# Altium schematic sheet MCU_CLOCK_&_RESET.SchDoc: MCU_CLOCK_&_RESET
size A4; Date: Not used; ApprovedBy: Not used; CheckedBy: Not used; Author: Not used; CompanyName: STMicroelectronics; DrawnBy: Not used; Engineer: Not used; Organization: Not used; Address1: Not used; Address2: Not used; Address3: Not used; Address4: Not used; DocumentNumber: 4; Revision: Not used; SheetNumber: 4; SheetTotal: 16
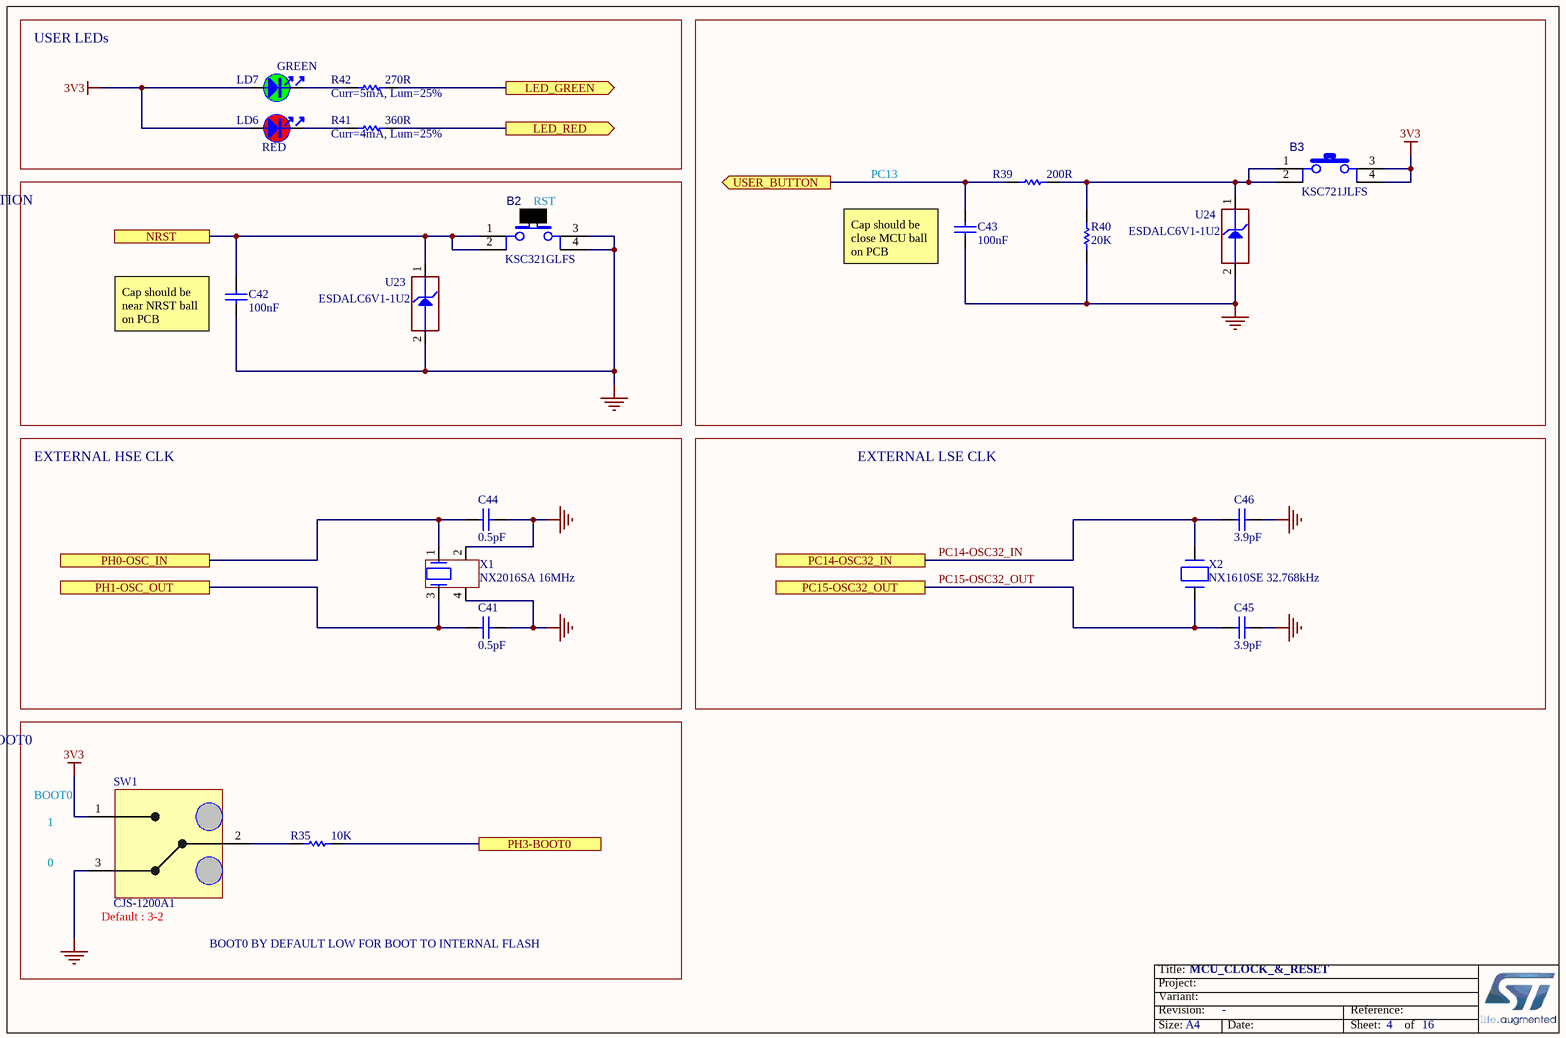
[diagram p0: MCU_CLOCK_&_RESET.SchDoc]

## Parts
B2  value KSC321GLFS  [SWI_C&K_KSC321GLFS_BLACK]  (hidden comment: SW_BLACK_KSC321GLFS)
B3  value KSC721JLFS  [SWI_C&K_KSC721JLFS_BLUE]  (hidden comment: SW_BLUE_KSC721JLFS)
C41  value 0.5pF  [C0402]  (hidden comment: Capacitor)
C42  value 100nF  [C0402]  (hidden comment: Capacitor)
C43  value 100nF  [C0402]
C44  value 0.5pF  [C0402]  (hidden comment: Capacitor)
C45  value 3.9pF  [C0402]  (hidden comment: Capacitor)
C46  value 3.9pF  [C0402]  (hidden comment: Capacitor)
LD6  value RED  [LED_0603_VISHAY_VLMS1300-GS08_RED_1A2K_H0P8]  (hidden comment: LED_red)
LD7  value GREEN  [LED_0603_OSRAM_LG-Q396-PS-35_GREEN_1A2K_H0P4]
R35  value 10K  [R0603]
R39  value 200R  [R0603]
R40  value 20K  [R0603]
R41  value 360R  [R0402]
R42  value 270R  [R0402]
SW1  CJS-1200A1  [SWI_CJS-1200A1]
U23  value ESDALC6V1-1U2  [ESD_ST0201]
U24  value ESDALC6V1-1U2  [ESD_ST0201]
X1  value NX2016SA 16MHz  [CRY_NX2016SA_4P]  (hidden comment: XTAL_4_PINS)
X2  value NX1610SE 32.768kHz  [CRY_NX1610SE_2P]  (hidden comment: XTAL_2_PINS)

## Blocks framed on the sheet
USER LEDs: LD6 LD7 R41 R42
PC13: B3 C43 R39 R40 U24
RESET FUNCTION: B2 C42 U23
EXTERNAL HSE CLK: C41 C44 X1
EXTERNAL LSE CLK: C45 C46 X2
PH3_BOOT0: R35 SW1

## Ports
LED_GREEN (out), LED_RED (out), NRST, PC14-OSC32_IN, PC15-OSC32_OUT, PH0-OSC_IN, PH1-OSC_OUT, PH3-BOOT0, USER_BUTTON (out)

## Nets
3V3: B3.3 B3.4 LD6.1 LD7.1 SW1.1
GND: B2.3 B2.4 C41.2 C42.1 C43.1 C44.2 C45.2 C46.2 R40.1 SW1.3 U23.2(GND) U24.2(GND) X1.2 X1.4
LED_GREEN: R42.2 ; port LED_GREEN
LED_RED: R41.2 ; port LED_RED
NRST: B2.1 B2.2 C42.2 U23.1(IO1) ; port NRST
PC14-OSC32_IN: C46.1 X2.2(X2) ; port PC14-OSC32_IN
PC15-OSC32_OUT: C45.1 X2.1(X1) ; port PC15-OSC32_OUT
PH0-OSC_IN: C44.1 X1.1 ; port PH0-OSC_IN
PH1-OSC_OUT: C41.1 X1.3 ; port PH1-OSC_OUT
PH3-BOOT0: R35.2 ; port PH3-BOOT0
USER_BUTTON: C43.2 R39.1 ; port USER_BUTTON
NetB3_1: B3.1 B3.2 R39.2 R40.2 U24.1(IO1)
NetLD6_2: LD6.2 R41.1
NetLD7_2: LD7.2 R42.1
NetR35_1: R35.1 SW1.2

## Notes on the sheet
- (near R42) Curr=5mA, Lum=25%
- (near R41) Curr=4mA, Lum=25%
- (near B2) RST
- (near C43) Cap should be close MCU ball on PCB
- (near C42) Cap should be near NRST ball on PCB
- (near SW1) BOOT0
- 1
- 0
- (near SW1) Default : 3-2
- BOOT0 BY DEFAULT LOW FOR BOOT TO INTERNAL FLASH

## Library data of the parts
B2 = MCD-00175: Switch HW BLACK High3.5mm 2Newtons; Part_Type: Misc; Manufacturer: C&K; Provided_By: SUBCO; Initial_Board_Reference: MB1274
B3 = MCD-01800: Switch HW BLUE High4.3mm 2.25 Newtons, BEND type; Part_Type: Misc; Manufacturer: C&K; Provided_By: SUBCO
C41 C44 = MCD-02215: Capacitor, MLCC, 0.5pF, 50V, C0G, +-0.1pF, 0402, T=0.5mm; Part_Preference: Recommended; Manufacturer: MURATA; Manufacturer_Part_Number: GJM1555C1HR50BB01D; Order_Code_RS: 723-5111P
C42 = MCD-00006: Capacitor, MLCC, 100nF, 16V, X7R, 10%, 0402, T=0.5mm; Manufacturer_Part_Number: CC0402KRX7R7BB104; Manufacturer: YAGEO; Provided_By: SUBCO; Initial_Board_Reference: MB1274
C43 = MCD-00006: Capacitor, MLCC, 100nF, 16V, X7R, 10%, 0402, T=0.5mm; Manufacturer_Part_Number: CC0402KRX7R7BB104; Manufacturer: YAGEO; Alternate_Manufacturer_Part_Number: GCM155R71C104KA55D; Alternate_Manufacturer: MURATA; Provided_By: SUBCO; ECCN_US: EAR99; ECCN_EU: NEC
C45 C46 = MCD-00556: Capacitor, MLCC, 3.9pF, 50V, NPO, +/-0.25pF, 0402, T=0.5mm; Part_Preference: Recommended; Manufacturer: YAGEO; Manufacturer_Part_Number: CC0402CRNPO9BN3R9; Component_Country_Of_Origin: China
LD6 = MCD-00587: LED Red, 0603 SMD, 2V Forward Voltage; Part_Type: Display; Manufacturer_Part_Number: VLMS1300-GS08; Manufacturer: VISHAY; Alternate_Manufacturer_Part_Number: LS Q976-NR-1; Alternate_Manufacturer: OSRAM OPTO SEMICONDUCTORS; Provided_By: SUBCO; Initial_Board_Reference: MB1331; Item Type: Item; Path: ws/MCD_ApplicationBoards/Lists/MCDPARTSdatabase
LD7 = MCD-00588: LED Green, 0603 SMD, Forward Voltage Typ=2V, Max=2.5V; Part_Type: Display; Manufacturer_Part_Number: LG Q396-PS-35; Manufacturer: OSRAM OPTO SEMICONDUCTORS; Alternate_Manufacturer_Part_Number: VLMTG1300-GS08; Alternate_Manufacturer: VISHAY SEMICONDUCTOR OPTO DIVISION; Provided_By: Subcon; Initial_Board_Reference: MB1331
R35 = MCD-00220: Resistor,10K,0603,1%,1/10W; Manufacturer_Part_Number: RC0603FR-0710KL; Manufacturer: YAGEO; Provided_By: Subcon; Initial_Board_Reference: MB1319
R39 = MCD-00418: Resistor,200R,0603,1%,1/10W; Manufacturer_Part_Number: RC0603FR-07200RL; Manufacturer: YAGEO; Provided_By: SUBCO; ECCN_US: EAR99; ECCN_EU: NEC
R40 = MCD-00422: Resistor,20K,0603,1%,1/10W; Manufacturer_Part_Number: RC0603FR-0720KL; Manufacturer: YAGEO; Provided_By: Subcon
R41 = MCD-00461: Resistor,360R,0402,1%,1/16W; Manufacturer_Part_Number: RC0402FR-07360RL; Manufacturer: YAGEO; Provided_By: Subcon
R42 = MCD-00441: Resistor,270R,0402,1%,1/16W; Manufacturer_Part_Number: RC0402FR-07270RL; Manufacturer: YAGEO; Provided_By: Subcon
SW1 = MCD-02279: SLIDE SWITCHE (SMD) serie CJS; Part_Preference: Recommended; Part_Type: Misc; Manufacturer: NIDEC Copal
U23 U24 = MCD-00170: ESD protection 6V1; Part_Type: Diode; Manufacturer: STMICROELECTRONICS; ECCN_US: EAR99; ECCN_EU: NEC; Provided_By: Subcon; Initial_Board_Reference: MB1274
X1 = MCD-01476: Crystal 16 MHz, 8pF, -+20 PPM, R=200Ω, SMD; Part_Type: Crystal_Osc; Manufacturer_Part_Number: NX2016SA 16 MHz EXS00A-CS07826; Manufacturer: NDK; Provided_By: ST; Initial_Board_Reference: MB1373; Item Type: Item; Path: ws/MCD_ApplicationBoards/Lists/MCDPARTSdatabase
X2 = MCD-02291: Crystal 32.768kHz, 9pF, -+20ppm, 70Kohm max, SMD; Part_Type: Crystal_Osc; Part_Preference: Recommended; Manufacturer: NDK; Manufacturer_Part_Number: NX1610SE 32.768KHz EXS00A-MU01499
